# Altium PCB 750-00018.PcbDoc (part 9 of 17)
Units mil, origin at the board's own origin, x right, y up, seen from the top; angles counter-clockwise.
Board outline 7086.64 x 6299.21 mil, 8 copper layers (Top Layer, L2, L3, L4, L5, L6, L7, Bottom Layer), stack 60.6 mil thick; 1356 components, 1054 nets, 4851 pads, 4296 vias.
Unrouted connection lines stored in the file: 12.
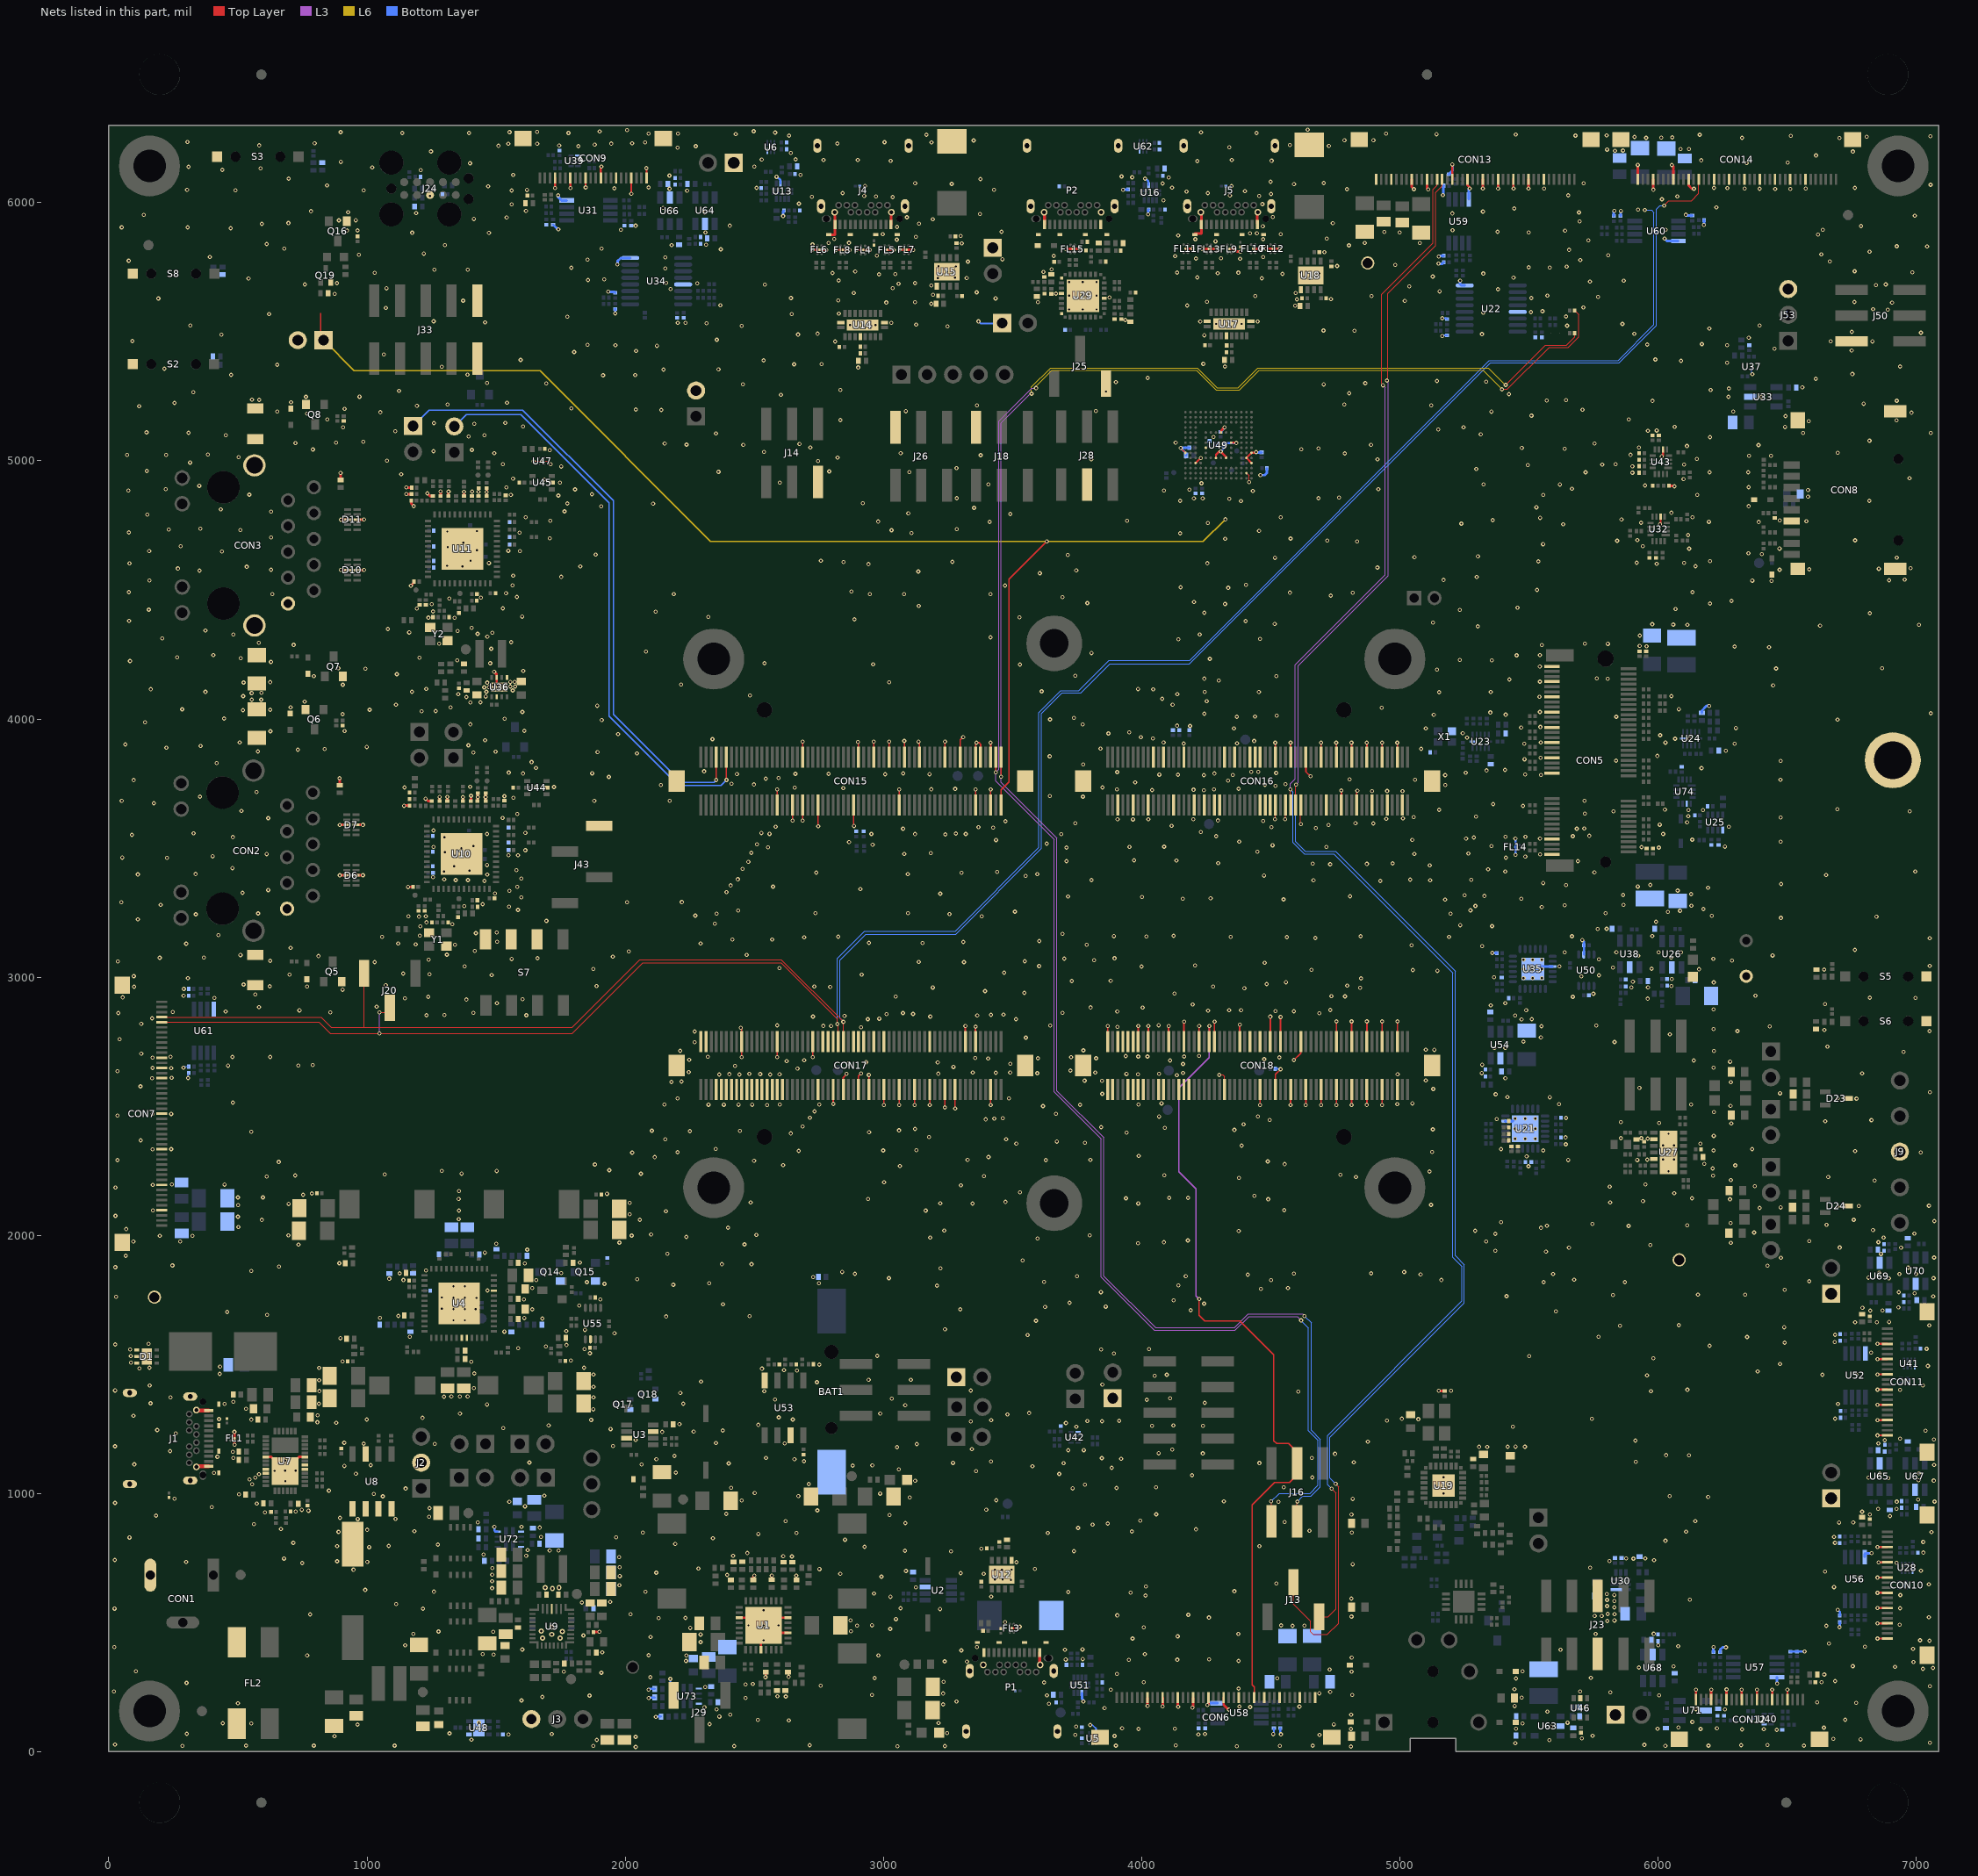
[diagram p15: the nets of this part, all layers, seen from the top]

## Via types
v1: diameter 16, hole 8, Top Layer to Bottom Layer, tented both sides, 3994 vias
v2: diameter 20, hole 10, Top Layer to Bottom Layer, tented both sides, 266 vias
v3: diameter 14, hole 7.87, Top Layer to Bottom Layer, tented both sides, 24 vias
v4: diameter 22, hole 12, Top Layer to Bottom Layer, tented both sides, 8 vias
v5: diameter 24, hole 12, Top Layer to Bottom Layer, tented both sides, 4 vias

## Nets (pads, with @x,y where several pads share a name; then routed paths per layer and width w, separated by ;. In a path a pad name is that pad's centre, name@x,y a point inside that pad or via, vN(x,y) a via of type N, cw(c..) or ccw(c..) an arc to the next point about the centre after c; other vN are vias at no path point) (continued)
GND: (continued)
  other v1: 2040.39,18.82 4368.14,20.94 4810.01,20.35 2421.41,21.87 3054.46,21.3 1876.39,22.46 3238.07,22.13 4534.68,23 285.15,23.13 531.55,23.98 793.94,23.93 1106.78,23.93 3900.09,23.59 4662.13,23.76 6028.07,23.31 6194.82,23.59 6564.89,23.9 4132.2,24.31 2714.05,25.2 6321.21,25.18 5946.82,26.86 6423.69,26.65 23.63,28.08 5447.04,32.94 7052.94,35.05 1890.01,45.72 5578.56,45.43 1404.05,46.32 6784.04,47.82 6678.84,49.85 5704.09,52.16 2040.25,57.91 874.03,60.75 3894.86,60.98 5746.09,62.33 3742.53,65.63 4688.88,65.45 1548.22,66.82 4219.37,67.44 1715.62,68.5 4245.14,68.49 301.65,69.6 1319.18,71.21 3246.05,72.5 6459.01,85.06 6325.13,86.8 6409.37,87.26 3987.17,88.5 4810.26,88.28 5997.65,89.05 6164.12,88.41 4128.44,89.27 5449.73,89.68 3924.07,91.09 6227.52,90.86 6642.11,93.54 6078.3,94.74 3746.14,97.44 5585.11,97.15 963.33,105.19 4743.97,105.64 2326.51,107.27 551.92,109.3 5475.46,109.92 440.82,110.66 3212.96,110.82 5649.39,112.47 1432.99,114.04 6132.32,115.29 2633.46,121.49 2513.96,123.03 6724.06,123.95 2364.45,136.26 2406.13,143.85 4811.16,143.71 5570.84,155.53 6258.85,163.89 2353.34,164.12 6146.24,164.75 3856.06,169 2306.7,172.08 4420.26,173.35 5720.93,173.72 4610.8,174.83 4378.5,175.17 5444.05,177.05 3231.43,183.37 3640.75,186.37 499.98,187.88 6767.15,189.91 6615.87,191.67 3282.63,194.42 1597.93,198.83 2465.48,208.2 5471.68,210.02 1679.32,212.27 2589.35,214.86 2621.67,214.13 1861.75,217.42 3633.01,217.97 6003.3,218.81 4815.53,219.88 2955.7,220.17 3230.93,225.72 4688.2,226.35 5815.4,230.56 4729.88,231.84 5698.07,233.58 19.24,234.11 3880.04,240.58 5443.74,242.04 4375.27,244.61 2309.55,250.42 7053,254.12 2756.8,255.63 2465.47,260.55 2494.02,262.84 301.12,266.62 3621.83,268.53 4007.75,268.91 6632.81,269.56 3232.17,271.05 6685.36,273.47 5449.08,283.79 4524.57,284.45 2965.72,285.7 5739.3,286.64 2097.11,288.98 2632.85,290.38 6643.49,299.15 3904.64,301.59 1907.61,305.96 1762.21,309.83 4812.91,310.43 5474.51,311.73 104.6,312.12 4728.08,318.74 7025.3,321.36 7064.27,324.45 5925.4,326.43 6917.55,328.88 6060.03,330.24 6753.96,331.51 6005.19,333.83 6988.65,348.05 3323.32,349.58 3237.13,350.32 2235.28,352.08 4374.75,351.76 3950.19,355.6 4137.81,356.68 3705.83,357.24 3771.38,358.95 4260.7,358.15 4813.18,365.08 768.12,373.32 2090.42,373.95 2236.34,373.46 2980.07,373.2 1490.35,376.67 1447.82,377.85 4012.29,378.6 1910.88,385.24 3301.56,392.71 3702.59,395.05 5621.87,395.67 1601.16,396.26 3770.48,396.37 6987.11,398.52 20.89,404.97 3361.84,405.19 6800.57,407.15 6077.91,409.12 6000.7,411.95 1147.36,412.23 6661.61,419.47 2291.56,424.99 7051.15,430.15 2535.26,431.68 7014.5,431.7 3964.35,438.45 2097.78,444.6 4139.28,447.13 1837.72,450.4 2291.73,454.1 1178.68,456.73 4374.05,456.29 5757.89,456.56 5982.8,456.97 1488.9,464.79 1276.59,465.57 2874.32,466.8 3025.98,475.9 2251.51,479.64 4008.35,482.34 4584.65,488.02 6650.95,487.66 2897.82,488.61 4630.42,488.39 2477.19,489.75 2593.33,489.75 2955.7,489.79 4539.62,489.51 6935.02,492.09 3470.5,502.54 5803.12,506.65 2872.74,508.71 5830.89,508.51 3048.2,513.63 2129.58,517.15 2233.5,518.66 4260.21,519.88 7048.6,520.61 4812.53,523.35 5781.55,525.72 5754.32,526.49 3905.3,528.39 4180.57,530.2 779.39,531.88 2020.45,532.45 5831.4,533.06 5804.98,533.57 2535.26,547.82 3219.46,552.73 21.99,554.41 1216.18,554.23 3066.52,555.73 6936.79,555.79 5830.55,559.31 5802.46,564.45 1112.97,571.74 1831.83,578 1941.42,580.7 5830.58,584.04 5802.18,588.38 6122.64,589.34 4811.84,593.46 3026.55,600.37 3417,601.1 4014.53,605.04 6937.73,606.63 5830.72,607.13 5801.9,611.33 2963.44,612.7 3956.83,616.66 3715.94,618.77 2078.14,619.83 1258.55,620.13 4358.92,621.84 993.04,626.93 1484.17,633.71 3126.04,636.84 6681.29,637.7 4016.33,639.73 1977.14,644.78 7048.6,648.14 4521.05,651.58 1483.95,660.11 3493.86,665.42 3431.01,667.36 3461.53,667.12 6779.37,675.05 2992.11,678.12 1978.55,680.2 2662.21,682.48 2394.63,684.98 1484.52,686.21 2832.62,689.16 3388.3,689.2 3298.6,691.64 2120.01,693.75 6646.79,697.39 3087.01,700.58 7017.56,701.52 3459.35,704.25 947.27,705.12 3431.25,705.46 3495.8,705.46 2752.1,707.46 3586.04,707.68 2283.35,709.78 1484.93,711.06 5736.53,713 1978.27,714.76 4817.19,726.17 749.06,731.16 6923.43,731.33 3515.05,734.57 299.32,735.37 1001.06,735.33 883.9,737.91 5811.87,738.78 5984.23,741.51 23.08,742.86 5904.04,747.96 678.26,748.2 5876.04,748.98 5949.97,748.68 1976,753.86 2645.28,756.43 2611.64,757.15 1616.52,758.6 2417.53,759.09 1451.34,763.91 2472.29,769.76 7027.15,771.42 3261.78,776.24 3737.25,777.07 3082.66,778.34 1707.18,779.87 1741.61,779.38 1621.64,780.9 3378.57,786.67 1008.06,792.44 2926.16,794.09 4455.68,796.07 883.9,796.12 1083.51,797.01 1274.24,802.14 2193.41,804.89 714.4,809.14 6684.91,809.34 7026.55,812.51 6028.13,817.37 2851.19,821.39 2339.18,826.6 80.11,829.82 1964.67,830.51 1673.9,832.15 6681.29,832.27 2515.12,843.45 2663.56,847.42 3636.55,847.71 4813.2,848.85 2068.17,849.56 889.43,851.76 6108.25,852.1 7058.5,851.18 1183.23,853.92 3961.57,853.4 4649.67,855.58 1000.32,859.86 4209.96,861.56 666.41,863.16 3753.5,866.98 1668.7,868.34 1598.13,870.79 3810.01,880.13 561.66,881.12 3868.27,884.07 3084.51,885.49 6701.05,887.67 6755.64,888.08 1429.06,888.68 4553.95,890.28 2620.81,893.73 6143.99,893.53 3994.04,895.33 963.78,901.24 1109.98,902.25 895.48,906.28 1240.58,910.07 6897.99,912.71 182.57,914.57 3023.4,916.84 4812.51,918.96 6820.02,918.68 4056.17,919.66 2390.97,921.23 604.85,927.62 6789.93,930.08 723.64,930.39 773.27,933.58 2743.82,934.75 747.27,936.99 3398.12,937.3 6923.05,940.65 6851.61,941.11 1241.65,943.35 398.32,947.87 1611.83,950.52 572.93,961.08 23.63,963.72 1550.75,967.87 4530.08,967.87 6924.31,968.6 7070.71,969 4318.35,970.26 2451.06,972.89 3436.95,974.19 7007.12,977.09 254.64,979.59 4817.42,979.44 3101.63,985.4 6193.54,987.27 1060.91,989.31 2670.49,989.97 6044.08,990.57 1686.4,992.24 503.87,996.57 1026.01,998.64 2986.86,999.84 5168.69,1000.24 2501.12,1002.11 852.04,1011.22 1149.05,1019.63 3732.35,1020.29 2409.94,1022 3902.53,1021.52 4055.17,1023.83 4550.19,1024.45 5137.19,1031.74 5168.69,1031.74 5200.19,1031.74 3780.45,1034.19 554.84,1036.09 2711.08,1037.14 683.33,1047.51 3122.75,1049.59 7067.35,1050.27 7008.65,1051.78 544.9,1054.62 6891.02,1059.42 566.59,1061.15 6814.71,1061.43 4660.54,1062.58 5168.69,1063.23 4194.97,1070.96 581.7,1075.59 3680.5,1075.88 956.84,1076.86 6858.85,1078.05 7009.73,1078.65 407.66,1080.41 2195.47,1080.9 3357.98,1086.71 642.01,1087.88 682.37,1088.36 723.22,1088.36 3058.89,1094.15 3883.28,1099.81 3576.93,1105.43 912.6,1107 2880.48,1108.38 1014.58,1110.01 2956.67,1109.32 7068.64,1110.64 2062.69,1113.02 98.77,1113.14 2400.28,1116.99 3269.07,1118.86 3697.61,1118.1 4455.95,1118.26 1628.68,1120.41 4821.46,1121.6 5913.79,1123.15 3415.83,1124.76 2691.57,1125.51 682.37,1128.24 2120.32,1132.78 2655.16,1132.61 3920.32,1134.84 3845.32,1137.4 481.6,1138.59 2545.03,1138.35 4659.2,1138.4 420.21,1142.5 2190.65,1145.54 6030.73,1148.85 6119.09,1148.59 4748.49,1153.96 4236.36,1155.61 4065.2,1156.3 480.72,1162.15 237.68,1164.46 3715.61,1167.72 3775.59,1168.14 4118.82,1170.76 3342.1,1172.12 3052.24,1179.56 5338.31,1180.97 5307.03,1181.16 5417.35,1181.37 5448.18,1181.76 5484.05,1181.57 23.63,1182.94 1952.67,1183.88 487.5,1188.71 3128.68,1191.57 1262.79,1192.41 986.54,1193.32 2617.63,1194.59 6852.75,1194.6 911.52,1196.63 2351.01,1196.16 4875.71,1201.42 5911.91,1205.02 6877.12,1207.04 2040.15,1208.29 7068.08,1209.19 6937.05,1212.83 259.67,1233.24 2143.28,1238.97 2264.84,1239.82 7035.59,1243.23 2377.84,1244.46 187.38,1246.07 1943.22,1249.75 1527.83,1253.53 3746.85,1258.77 5437.57,1258.65 4039.8,1262.31 4237.63,1262.13 1703.17,1264.09 4122.49,1263.54 2515.2,1266.18 2209.79,1268.81 3706.37,1273.38 880.88,1274.5 807.81,1276.37 3337.91,1278.95 3846.67,1279.99 3789.45,1280.6 3912.6,1281.78 4949.77,1282.82 3417.11,1284.18 1868.08,1285.23 551.49,1286.59 998.33,1286.72 2648.49,1286.93 426.88,1288.75 5071.3,1288.28 5007.2,1289.99 5743.87,1289.12 6684.98,1290.27 1214.99,1293.36 2594.4,1295.26 95.27,1300.87 808.77,1303.34 3479.99,1305.93 1359.81,1309.86 2987.26,1310.19 3563.85,1312.06 1876.49,1326.21 531.4,1328.13 3084.24,1342.24 1464.28,1344.91 447.75,1347.4 2224.44,1348.06 6696.56,1347.63 813.91,1348.29 161.73,1349.84 4243.85,1351.25 481.82,1355.73 4020.06,1363.19 2580.11,1364.12 3032.17,1367.74 4110.15,1369.36 1876.71,1373.04 238.68,1373.16 1297.61,1375.2 1358.93,1375.64 1389.28,1375.83 1326.4,1376.51 2213.15,1389.68 4606,1395.15 5972.16,1396.01 815.19,1397.09 2538.24,1396.24 5197.71,1397.93 3337.91,1398.88 24.18,1399.4 6936.81,1401.37 6113.17,1402.16 1413.58,1408.55 1876.94,1413.05 158.23,1418.63 7025.72,1418.14 3847.52,1422 2742.03,1431.42 2293.4,1434.01 814.55,1439.47 2942.51,1440.88 3106,1440.23 4050.81,1455.64 5957,1457.22 1876.94,1461.02 4097,1460.44 6636.18,1460.25 6767.81,1461.59 429.25,1463.78 1415.5,1465.42 6385.18,1472.75 2664.6,1476.39 2614.92,1477.77 2529.4,1483.71 118.56,1484.68 814.23,1486.67 157.58,1487.22 1840.79,1487.7 430.43,1491.77 7044.68,1494.1 2751.52,1499.36 6472.31,1502.18 85.59,1506.92 1403.09,1510.37 905.09,1511.71 1789.71,1515.99 5981.7,1524.32 84.81,1532.67 5500.93,1532.87 2975.9,1533.34 3892.38,1542.99 1862.95,1543.66 6825.1,1546.12 82.86,1557.84 3842.59,1558.15 1842.43,1559.83 4028.71,1559.4 7039.99,1560.8 1585.63,1563.57 1692.37,1570.05 6198.92,1572.56 1772.62,1575.59 24.73,1577.41 153.66,1580.54 6490.05,1584.48 6684.18,1587.26 897.06,1601.61 1165.53,1607 6344.64,1606.69 5768.77,1607.15 3558.17,1613.82 6685.9,1614.89 1958.21,1620.68 1531.9,1627.16 1771.52,1628.92 1843.97,1633.95 3238.32,1635.91 6487.91,1644.21 5852.65,1649.66 7049.91,1651.68 6079.84,1652.45 6762.91,1663.82 6846.72,1663.82 6894.44,1664.57 3590.48,1669.41 1334.73,1671.04 1378.63,1671.04 1678.5,1677.71 1609.1,1679.82 1050.31,1680.19 2157.92,1686.03 2480.8,1686.94 1121.28,1687.98 613.37,1691.84 458.25,1703.41 5604.47,1705.73 6820.95,1708.56 6868.82,1709.53 4189.99,1710.39 1420.57,1714.1 1639.98,1713.49 3297.61,1713.55 1334.73,1714.94 1378.63,1714.94 1290.01,1715.8 6791.37,1719.26 6930.74,1721.02 3625.89,1723.26 3860.72,1724.05 1821.37,1727.74 2378.62,1732.74 4241.64,1735.59 3721.07,1739.31 4123.64,1748.65 1607.77,1752.05 1903.31,1751.89 1423.35,1757.96 1334.73,1758.83 1378.63,1758.83 1290.01,1759.7 28.03,1762.01 7065.17,1763.34 5412.99,1764.53 5825.04,1769.2 6154.41,1770.65 6337.26,1770.59 6993.52,1775.41 6932.1,1780 3842.07,1780.14 1466.51,1786.81 6490.16,1789.17 4461.42,1792.75 1639.69,1796.48 4566.46,1796.35 1334.73,1802.73 1378.63,1802.73 3207.14,1805.19 4141.7,1806.02 2186.01,1808.64 1919.62,1812.11 2325.02,1814.98 2750.33,1815.05 1851.23,1818.77 5871.5,1818.85 5557.08,1819.18 3622.22,1820.13 6585.32,1822.33 1654.72,1826.54 4501.28,1826.27 1140.59,1827.11 5160.67,1827.12 5674.77,1828.71 2045.95,1829.72 1086.03,1832.23 6893.74,1833.44 3020.79,1834.38 7066.77,1834.12 6814.69,1836.29 2727.36,1838.57 3749.44,1841.52 4170.53,1841.58 4410.36,1848.04 5080.05,1848.88 6934.53,1849.94 6998.8,1849.94 5593.12,1850.31 2888.99,1851.37 4589.7,1851.8 1126.31,1853.07 4888.21,1852.9 1751.47,1853.9 6856.3,1855.68 5016.53,1857.97 2840.26,1858.38 551.7,1862.19 1228.63,1863.96 3220.34,1872.69 6968.71,1874.85 25.28,1876.84 658.9,1879.81 6423.69,1882.23 246.3,1883.51 2374.21,1888.4 2488.76,1888.4 1610.83,1890.79 892.52,1892.03 1824,1894.36 3538.73,1902.94 6475.46,1913.26 7069.03,1913.92 65.51,1921 6862.91,1928.08 2163.11,1928.58 1455.81,1933.16 5565.66,1936.69 5369.63,1940.88 1620.06,1944.81 5654.69,1952.15 6703.3,1952.98 6941.02,1952.29 5969.79,1962.47 734.28,1963.83 2461.85,1965.3 1500.56,1967.75 3985.53,1969.07 6281.44,1971.04 1977.14,1972.08 4086.35,1973.35 6852.98,1973.52 5333.54,1975.82 94.91,1976.11 276.65,1976.18 6585.32,1978.31 4178.82,1980.55 3596.9,1987.8 3181.01,1991.55 6873.03,1991.75 2236.07,1993.87 197.45,1998.01 323.69,1998.31 695.52,1999.61 2024.9,1999.25 3798.43,2000.36 2507.67,2001.49 2099.88,2003.35 5369.63,2006.08 6992.46,2007.02 6371.96,2011.12 4375.67,2017.03 5290.9,2017.75 3235.24,2018.55 6832.17,2019.97 66.89,2024.34 2398.27,2029.82 5545.99,2029.48 501.62,2032.48 5885.51,2036.4 5569.54,2037.18 6112.71,2038.83 6652.27,2040.56 5744.9,2044.66 6280.61,2048.04 5391.86,2050.54 7069.35,2055.16 592.73,2060.09 2055.85,2060.5 6757.59,2060.46 1355.2,2062.6 499.79,2072.2 25.71,2075.61 2016.83,2081.34 2157.51,2093.3 3163.49,2096.06 170.87,2096.94 1355.48,2096.19 4552.03,2097.84 6392.7,2106.36 6474.37,2108.29 6694.87,2111.83 6776.87,2114.08 7048.69,2114.84 500.31,2116.89 5120.36,2117.98 696.37,2121.85 3344.41,2123.51 3986.66,2123.54 3219.75,2124.57 2017.3,2126.16 2485.52,2127.94 5814.11,2127.51 3471.95,2129.8 5941.4,2132.81 4489.86,2139.93 6278.13,2139.94 1354.66,2141.24 2940.25,2141.33 3939.11,2143.53 6131.64,2143.9 4106.59,2145.21 4179.33,2145.21 499.79,2146.94 596.79,2147.23 4436.31,2152.73 752.19,2157.36 1929.28,2160.95 786.66,2162.52 6062.19,2162.89 3528.47,2166.15 1355.75,2171.69 25.71,2185.81 5812.41,2188.88 6374.79,2190.3 3300.03,2193.91 170.28,2195.56 243.66,2196.98 448.2,2196.7 5950.76,2197.37 3002.06,2205.29 6838.37,2212.99 6281.44,2214.45 4376.62,2222.9 4829.71,2226.06 6658.76,2226.41 610.85,2228.07 3389.13,2229.72 6212.68,2230.93 721.89,2232.31 4088.01,2232.49 4769.49,2234.88 1068.21,2236.3 2060.41,2238.8 1365.83,2239.21 5114.21,2247.57 6040.4,2248.14 1502.31,2249.37 1289.9,2250.41 1938.3,2252.56 6211.4,2259.44 5497.7,2267.54 3063.3,2268.39 6298.47,2271.42 2611.46,2272.24 1882.29,2274.33 4553.93,2275.99 6179.3,2277.27 658.04,2284.46 4488.19,2286.65 2498.76,2289.09 33.02,2291.53 3628.77,2291.73 5651.51,2291.9 5919.27,2291.89 3325.59,2292.32 3801.53,2292.25 5957.89,2293.43 6018.74,2293.81 6062.05,2293.81 2113.84,2303.22 3406.57,2303.53 5490.84,2305.63 3988.35,2307.33 2026.76,2320.5 7016.94,2321.37 2201.98,2322.34 5124.83,2322.89 6763.02,2326.53 2671.97,2327.19 5555.24,2329 6214.84,2328.91 2998.85,2329.16 3126.93,2329.55 169.34,2333.51 241.54,2334.01 5391.8,2334.04 2350.23,2334.51 6363.74,2334.18 4387.01,2347.56 6018.74,2348.14 6062.05,2348.14 5642.62,2352.87 6163.81,2355.03 3514.3,2355.58 3779.94,2358.71 3671.36,2363.27 123.62,2367.95 2155.26,2372.81 3475.01,2372.59 5445.89,2373.8 5485.26,2373.8 5524.63,2373.8 5959.56,2374.66 5856.15,2376.37 5934.7,2376.5 5641.81,2379.65 3176.99,2380.69 6215.27,2385.4 6040.4,2393.81 2640.9,2394.94 3941.57,2397.98 2944.21,2399.29 551.84,2401.72 2249.65,2403.62 2444.14,2405.09 2103,2405.7 3060.27,2406.85 4358.89,2408.54 5127.45,2410.42 3121.99,2412.25 5445.89,2413.17 5485.26,2413.17 5524.63,2413.17 4089.33,2416.83 3843.25,2419.17 2686.95,2422.11 4394.52,2429.74 6283.5,2433.98 6003.71,2435.51 5856.04,2438.15 6647.26,2442.21 6825.98,2446.26 4496.12,2447.2 3395.44,2449.37 5374.77,2450.56 3429.15,2452.56 5485.26,2452.54 5524.63,2452.54 3462.52,2453.9 5643.27,2454.98 2714.99,2455.97 4067.5,2460.15 4449.87,2460.73 33.02,2464.48 241.29,2470.41 3667.71,2470.94 169.59,2471.16 6216.29,2477.58 2733.3,2480.12 3617.72,2500.65 6280.28,2502.02 3001.88,2504.74 3060.93,2504.74 3119.99,2504.74 3179.04,2504.74 3415.26,2504.74 4458.5,2504.58 4576.62,2504.58 4635.67,2504.58 4694.73,2504.58 4753.78,2504.58 4812.84,2504.58 2322.29,2506.04 2381.62,2506.04 2438.38,2506.04 2491.16,2506.04 2549.09,2505.34 3761.66,2505.86 2151.6,2506.65 2598.14,2506.5 2751.9,2506.76 3987.34,2506.66 6128,2506.72 2805.6,2509.02 4989.57,2508.64 5616.2,2508.44 4076.87,2511.18 5048.13,2511.2 480.03,2514.19 6768.18,2529.38 2202.37,2530.8 3485.75,2530.43 6695.43,2530.58 5580.67,2534.97 5416.34,2535.39 5370.78,2546.52 3847.22,2548.47 6471.82,2550.29 7052.46,2554.42 5128.81,2566.74 5927.77,2571.58 122.67,2577.03 2178.34,2594.08 6281.68,2593.27 2217.93,2595.8 3846.42,2598.02 3778.92,2599.09 5100.16,2600.3 167.57,2608.21 5408.2,2608.28 242.91,2609.94 4136.14,2620.92 2442.17,2623.03 2363.81,2623.27 2561.35,2623.3 3985.97,2623.47 4991.05,2623.84 2403.23,2624.48 2522.58,2624.9 2597.45,2624.37 3940.97,2625.08 2480.63,2625.2 4066.96,2626.03 3212.62,2626.17 6789.85,2626.9 3595.73,2628.41 5316.53,2628.49 3434.69,2630.08 4160.04,2629.46 3490.54,2630.41 3820.17,2630.97 2245.97,2632 3345.58,2631.13 33.51,2635.49 3723.74,2638.47 2667.11,2645.64 241.42,2647.61 169.3,2648.6 6214.64,2649.12 3270.83,2652.3 2425.27,2656.57 461.51,2657.35 733.3,2658.3 789.88,2659.41 5318.35,2660.74 4160.08,2663.93 3491.06,2664.52 2864.26,2666.07 2932.37,2670.49 3209.98,2670.16 6278.52,2672.7 2624.93,2675.27 4109.47,2677.72 6138.19,2677.58 2693.14,2678.44 2247.28,2680.07 4474.71,2682.44 3405.01,2684.67 3598.59,2685.74 3355.17,2687.03 3823.38,2686.15 169.06,2688.26 2450.69,2689.78 2588.49,2689.78 2726.29,2689.78 4533.15,2689.45 478.18,2691.04 3726.68,2690.17 239.38,2691.8 624.91,2691.19 2320.13,2691.67 3986.78,2692.84 4022.14,2692.58 4164.21,2692.8 3937.76,2694.45 4221.87,2694.89 125.59,2703.7 6950.88,2710.51 6215.96,2713.83 2212.98,2714.81 3774.36,2716.42 5133.76,2718.59 5100.16,2719.48 5366.65,2725.47 5407.91,2726.41 6655.67,2731.15 2268.93,2747.96 5831.05,2749.07 5478.16,2750.52 41.3,2760.22 3551.19,2765.84 5545.82,2767.16 6045.17,2778.79 2268.93,2789.61 6307.1,2791.26 7051.2,2791.17 6643.65,2795.48 6214.97,2798.95 2912.6,2805.6 3905.79,2807.25 3356.49,2808.17 6432.48,2808.93 5548.51,2809.9 2796.91,2810.81 3317.12,2810.54 3868.3,2810.54 3986.41,2810.54 4025.78,2810.54 4104.52,2810.54 4222.63,2810.54 2767.1,2811.44 3645.68,2812.25 5760.58,2812.74 2588.43,2813.29 4066.16,2813.78 4379.9,2816.4 125.59,2819.65 4164.25,2828.35 4282.36,2828.35 5471.01,2836.54 5510.57,2837.05 2939.63,2837.29 3513.56,2837.4 2983.49,2839.33 167.07,2840.48 2726.67,2847.35 3181.07,2847.69 2848.97,2850.03 3362.98,2852.02 5446.55,2851.9 1230.06,2852.37 1616.54,2852.6 1300.06,2853.8 3415.98,2854.33 3464.6,2855.11 3011.53,2857.32 3114.49,2857.52 4688.05,2860.09 36.92,2861.07 3075.65,2860.87 1412.26,2861.48 3693.62,2861.81 857.66,2863.96 247.21,2864.93 452.09,2867.21 3905.34,2867.51 4589.72,2867.72 4517.8,2869.23 4257.07,2870.29 738.21,2871.56 5489.13,2872.02 4338.69,2872.18 4384.74,2872.51 4730.73,2872.83 6214.11,2875.5 3802.5,2882.89 4003.8,2882.51 581.3,2884.04 1036.95,2885.42 5351.55,2891 4197.23,2893.84 6646.8,2896.13 1503.08,2898.87 5407.95,2899.38 1384.52,2913.46 1601.98,2915.05 5959.51,2916.91 1146.36,2917.6 408.76,2919.75 6996.2,2919.43 6819.61,2920.76 53.29,2921.94 1236.96,2924.04 3047.08,2924.56 5669.86,2924.23 4787.27,2925.9 4734.64,2926.6 289.4,2927.93 6376.72,2928.22 567.5,2932.95 5749.22,2935.72 4126.99,2937 3545.36,2939.18 3393.23,2946.07 904.88,2951.46 290.45,2954.54 4397.68,2956.84 4845.69,2958.65 3190.92,2960 5896.53,2960.15 5960.67,2960.73 2793.48,2961.94 97.88,2963.12 767.47,2963.5 2732.13,2963.62 4276.06,2963.5 623.43,2964.55 1888.84,2965.73 6051.26,2965.48 4795.83,2967.5 1072.5,2969.12 521.99,2971.82 4483.8,2973.4 6215.27,2979.8 4558.95,2980.43 5902.21,2982.51 3728.9,2985.21 3879.84,2986.11 6053.35,2992.35 4849.23,2995.53 306.21,2996.31 5478.96,2996.43 5514.39,2996.43 5549.82,2996.43 5364.98,2999.16 96.64,3003.82 5702.94,3003.28 5770.93,3007.49 1482.7,3008.48 699.77,3009.62 2915.75,3010.03 1241.48,3011.78 1140.35,3014.21 3466.79,3017.61 5145.59,3024.55 5050.27,3027.67 4657.76,3028.91 6642.45,3029.41 6158.5,3030.78 5478.96,3031.87 5514.39,3031.87 5549.82,3031.87 1876.2,3032.17 5974.63,3032.6 2596.94,3034.85 5825.45,3037.21 3999.06,3041.24 1378.02,3042.29 5618.05,3042.1 3602.76,3043.19 7051.7,3043.76 4206.75,3045.97 4476.04,3055.45 1029.13,3058.44 3136.72,3059.02 3311.57,3058.13 3547.48,3061.63 6286.07,3063.89 3815.92,3065.77 1238.29,3067.5 5478.96,3067.3 5514.39,3067.3 5549.82,3067.3 5770.35,3069.2 1560.22,3070.52 3699.75,3071.9 6213.71,3071.22 1659.9,3073.45 3894.65,3073.3 6050.56,3075.74 1951.44,3079.21 812.22,3081.76 5922.95,3083.14 6443.42,3084.08 2469.95,3086.39 1309.26,3087.37 5638.49,3096.37 5838.22,3096.36 6001.74,3097.03 6088.81,3097.03 2013.81,3099.49 1416.73,3101.84 6761.7,3105.67 703.88,3113.79 5318.45,3120.32 5044.66,3123.61 1340.95,3125.14 3787.08,3125.22 1188.32,3127.25 1120.13,3130.09 2291.47,3130.12 3151.02,3131.89 2943.83,3133.23 1503.98,3136.98 3309.11,3136.42 3603.62,3139.95 2415.3,3145.88 2568.62,3145.85 4672.72,3151.65 7051.85,3151.38 2693.1,3154.68 4562.11,3154.95 4344.16,3155.74 5190.2,3155.89 1058.39,3156.35 2824.8,3157.09 4017.81,3157.54 3892.72,3158.93 4848.02,3158.4 5666.08,3158.81 5977.19,3159.66 4123.04,3160.48 1204.93,3161.19 3692.91,3167.62 1421.35,3170.63 1501.72,3172.71 5765.52,3187.04 5800.7,3187.3 1205.99,3196.35 5357.06,3197.45 5233.99,3201.35 1330.51,3205.17 2347.38,3207.46 1229.94,3212.71 5991.48,3214.66 1694.66,3217.99 6475.62,3229.69 1201.41,3234.78 6845.79,3234.12 1227.66,3235.92 3380.81,3235.82 1160.35,3236.32 6208.13,3237.36 2271.39,3238.7 3255.53,3244.21 2353.89,3245.74 5196.06,3246.29 3094.9,3247.41 5796.29,3247.96 2736.34,3248.23 3508.97,3253.8 6037.22,3253.35 6084.77,3257 2437.27,3258.03 5273.24,3259 1584.23,3260.45 6175.36,3263.78 5549.28,3271.95 1549.64,3273.11 1376.14,3275.14 5292.11,3275.75 6128.87,3277.14 5638.37,3278.38 5865.8,3280.14 1447.77,3282.51 2007.24,3290.3 2218.93,3290.91 5174.9,3300.41 4549.28,3301.43 4159.66,3304.04 5469.51,3304.06 4266.87,3305.73 1597.27,3309.25 4001.24,3310.53 3714.75,3312.27 4806.67,3313.4 5326.82,3314.73 5250.54,3317.37 5864.81,3318.5 6127.8,3321.57 3219.82,3323.27 1495.71,3324.56 2391.85,3329.8 1551.36,3334.36 6075.67,3335.63 2910.5,3341.17 6193.11,3346.11 1582.23,3349.48 2572.12,3350.69 5921.14,3351.01 2407.99,3355.51 5643.53,3356.62 5969.96,3357.45 6476.41,3360.89 5555.14,3364.6 1454.7,3373.04 4924.62,3372.76 1343.12,3376.02 3805.7,3375.97 4665.27,3375.51 5117.34,3375.28 1390.48,3376.44 5039.92,3377.81 5275.92,3377.31 1298.89,3379.16 2435.9,3379.34 1596.73,3382.28 1255.99,3387.04 3550.11,3391.85 4473.58,3393.45 894.51,3394.6 984.09,3394.93 6650.58,3396.22 1465.37,3397.76 3094.27,3398.68 3595.68,3399.47 3302.21,3403.76 2740.11,3404.92 5753.21,3405.74 3440.56,3408.1 5407.96,3409.02 6995.76,3408.94 1298.2,3409.46 1396.95,3412.88 1578.95,3414.74 5341.32,3418 2453.6,3419.16 1336.74,3430.21 5115.66,3433.35 1464.86,3434.27 4729.81,3437.56 4872.03,3438.82 4662,3440.13 4972.17,3440.92 4296.06,3441.75 2476.74,3446.73 3708.71,3449.07 5689.57,3449.37 4134.31,3451.96 3970,3452.69 5410.45,3463.14 5485.74,3467.48 1547.6,3471.87 1584.39,3472.18 5542.74,3475.57 3080.65,3476.87 5056.17,3477.82 5265,3479.33 2487.97,3481.44 3183.31,3481.12 1301.16,3484.5 4448.12,3485.47 1613.09,3491.91 1365.02,3499.55 3708.71,3501.91 6003.05,3501.97 2552.53,3502.86 5936.18,3503.63 1257.18,3504.89 3952.63,3504.8 4714.91,3504.11 4086.7,3505.53 6258.89,3505.72 5354.17,3507.91 1411.78,3508.44 4506.67,3510.77 2957.77,3512.84 2510.43,3515.13 3632.6,3517.18 2866.56,3523.53 4377.54,3524.53 6474.43,3524.97 3435.82,3531.17 5047.77,3532.07 6131.86,3532.78 5256.22,3536.73 5542.5,3536.58 5286.36,3541.09 1300.25,3541.74 5486.19,3543.56 5408.87,3544.13 4288.58,3546.4 5669.79,3546.23 5733.42,3547.63 3239.07,3553.19 3687.82,3553.74 1464.57,3554.64 2558.42,3554.95 2952.82,3554.51 3122.04,3554.37 3318.52,3554.77 6019.59,3554.68 3280.67,3556.15 1613.1,3559.09 2527.11,3558.36 4229,3562.15 1256.78,3568.48 3075.72,3574.9 5685.11,3575.32 5713.98,3576.33 4674.41,3577.51 3424.31,3579.42 3367.82,3580.98 4502.51,3581.47 2582.24,3582.52 6273.72,3582.41 4115.63,3586.26 894.51,3589.76 984.09,3590.09 4723.19,3589.75 6006.23,3590.71 3742.68,3595.99 4897.19,3595.27 4827.88,3596.75 6112,3599.44 3472.43,3604.03 4470.36,3604.4 2647.55,3606.22 2686.92,3606.22 4295.06,3607.09 3966.06,3611.07 3906.4,3611.82 4025.71,3611.86 4200.17,3611.24 4947.36,3613.02 5011.54,3614.93 1524.95,3616.95 6474.43,3618.34 5053.78,3620.09 5294.52,3622.17 6116.75,3623.86 1581.71,3631.61 5716,3633.85 6974.22,3641.77 5827.2,3642.38 6173.89,3646.95 6117.5,3647.1 5152.42,3648.38 6026.32,3648.71 6694.16,3650.92 5476.94,3663.44 5360.71,3670.41 5714.89,3682.74 1879.97,3683.18 2171.34,3683.27 1566.29,3694.8 3772.53,3699.18 1531.82,3700.97 3644.26,3701.52 4892.36,3720.84 4950.71,3720.98 5009.82,3720.81 4240.99,3723.81 4773.16,3723.13 4039.79,3724.5 4200.97,3726.06 2588.68,3727.54 3061.12,3727.54 3185.19,3727.8 3356.4,3727.54 3415.45,3727.54 3903.95,3727.28 4280.1,3727.23 3277.81,3729.5 4375.14,3729.75 2844.21,3732.52 1144.79,3734.85 2656.39,3734.17 3848.07,3734.81 1724,3736.81 1399.28,3737.79 1654.09,3739.17 4517.66,3741.01 2137.48,3744.65 4477.24,3745.08 5176.05,3744.12 2498.64,3746.47 4556.6,3748.07 2411.35,3749.03 3974.75,3754.03 4334.23,3760.85 5058.12,3764.8 6473.86,3764.9 4804.97,3766.13 2544,3769.11 893.4,3770.61 2593.25,3771.8 1936.42,3775.66 4241.01,3782.55 5175.2,3782.61 5546.05,3782.85 4140.97,3784.07 4353.2,3783.7 4068.24,3784.55 3006.58,3785.95 5484.96,3785.31 2432.49,3786.75 3178.49,3786.24 2658.93,3787.6 2787.14,3787.5 1603.57,3788.99 3076.1,3789.06 4281.16,3788.96 1871.85,3789.63 4520.7,3790.85 1548.59,3792.39 5254.76,3792.22 3904.97,3794.55 4424.11,3795.19 4451.51,3795.39 2305.15,3797.55 5335.32,3800.85 5407.07,3803.02 6168.11,3809.51 1653.94,3810.48 3772.78,3824.46 1636.94,3833.22 6474.87,3837.26 5837.59,3838.74 5482.65,3844.02 5544.25,3849.36 3643.48,3855.53 5996.87,3857.04 2045.37,3866.88 1411.65,3870.06 1892.51,3871.88 1497.58,3873.67 6262.24,3876.86 732.29,3881.3 835.18,3883.36 5082.6,3884.42 3840.67,3885.84 998.79,3891.59 1392.52,3898.2 4162.37,3904.75 5482.11,3904.39 6295.62,3904.2 4369,3905.57 4517.25,3908.17 4576.31,3908.17 4694.42,3908.17 4753.47,3908.17 4812.53,3908.17 4871.58,3908.17 4930.64,3908.17 4989.69,3908.17 5545.43,3908.86 6028.12,3908.57 4084.92,3909.52 2687.11,3912.58 2962.7,3912.58 3021.75,3912.58 3238.29,3912.58 3080.71,3914.94 4435.46,3914.77 1457.18,3918.07 2337.54,3922.1 6065.99,3923.61 6121.39,3923.97 4043.56,3924.55 5260.19,3928.02 3996.9,3929.63 6008.17,3937.35 1972.19,3940.99 3870.91,3943.95 5243.28,3945.27 3952.27,3947.8 912.83,3953.29 1609.02,3954.43 4357.11,3963.7 5100.16,3963.33 6301.29,3964.7 5469.34,3966.52 5543.85,3969.16 4187.41,3972.81 4137.15,3974.29 3771.76,3978.91 1400.2,3979.43 1908.9,3996.26 6694.87,3997.52 3645.04,3998.64 1532.22,4001 3737.77,4004.4 4367.98,4008.64 5837.79,4008.6 4438.94,4009.7 4522.99,4012.44 5131,4015.88 5409.36,4016.8 905.08,4018.73 4242.48,4020.68 7056.12,4021.96 5349.87,4025.29 1601.62,4027.42 5542.15,4027.16 1210.85,4030.15 1265.85,4030.85 519.7,4034.12 625.06,4035.86 1010.11,4035.65 6080.31,4037.78 4929.09,4043.36 703.72,4044.66 1323.96,4044.79 1891,4051.43 1111.98,4055.2 4119.5,4055.52 1399.69,4064.29 1439.2,4064.58 758.24,4067.65 4251.66,4068.47 553.84,4074.66 589.98,4074.82 4078.93,4078.42 1384.4,4085.05 5540.29,4085.52 1459.12,4087.07 520.15,4088.49 6051.79,4088.72 2483.12,4091.45 1353.25,4096.01 4137.96,4095.68 552.86,4100.49 590.47,4101.48 5151.9,4103.82 4243.95,4104.48 5351.96,4104.5 1173.71,4105.62 1461.99,4105.29 4453.82,4105.13 3612.39,4107.38 1563.91,4110.57 1488.85,4114.02 1504.41,4114.02 1519.98,4114.02 1535.54,4114.02 4044.42,4114.37 3985.75,4115.96 1229.25,4116.27 1453.39,4122.4 1471.22,4122.87 1554.32,4125.87 1573.25,4125.69 6445.15,4130.37 906.13,4132.84 1488.85,4132.4 1504.41,4132.4 1519.98,4132.4 1535.54,4132.4 2216.38,4133.74 1465.33,4140.94 522.13,4141.21 624.71,4142.6 3022.18,4142.54 1554.59,4143.18 1572,4143.72 5541.95,4144.42 4298.26,4148.69 5424.34,4153.28 5804.66,4155.44 4242.74,4156.21 5762.49,4157.4 793.93,4165.96 4521.61,4166 3742.78,4167.21 1115.06,4173.53 1604.77,4186.43 5143.86,4191.64 889.38,4195.97 993.64,4195.14 6456.76,4195.81 6867.33,4196.91 5541.81,4203.32 3528.03,4210.93 2959.6,4211.39 2539.23,4215.88 1477.03,4216.1 1348.93,4226.95 5355.91,4226.86 5231.61,4229.03 4263.6,4232.95 1202.53,4237.32 5451.87,4246.75 5542.17,4247.05 3805.67,4255.41 2079.75,4261.42 1480.68,4272.18 6429.61,4277.76 6296.15,4280.56 5955.42,4281.51 5928.37,4283.07 5549.34,4286.32 715.99,4287.13 1279.21,4291.55 5716.43,4291.37 5805.36,4291.1 1557.99,4297.4 4141.76,4308.97 4458.3,4310.53 3415.06,4316.48 1465.75,4318.96 5928.44,4323.02 4224.62,4327.61 1428.25,4329.92 1485.25,4333.93 1163.16,4335.31 1350.8,4340.5 1080.08,4348.45 1404.79,4352.54 5301.82,4358.75 6627.05,4361.8 6113.5,4364.76 6058.68,4365.77 7009.85,4365.11 5977.22,4367.03 4515.01,4367.81 5127.84,4373.25 4402.12,4379.34 2887.66,4386.14 1237.53,4392.53 1338.84,4392.16 3526.49,4393.47 2321.28,4395.6 1601.02,4396.51 6819.28,4409.86 4242.61,4411.31 2117.16,4415.94 1255.31,4416.74 5232.38,4422.08 6067.43,4426.08 1192.73,4427.89 1525.63,4428.46 5455.67,4430.97 3136.53,4437.77 1250.16,4444.39 4322.89,4445.38 6200.79,4447.12 3789.57,4448.69 4202.41,4452.99 6283.93,4457.57 1318.38,4467.09 1440.48,4470.45 3692.93,4471.7 1579.84,4472.9 4732.1,4477.63 3080.03,4483.59 2187.91,4484.25 2946.63,4484.18 3415.06,4484.16 1538.29,4487.38 4817.2,4488.9 4574.09,4489.44 6133.22,4491.16 2875.42,4493.55 5531.25,4500.01 4334.9,4508.07 4151.05,4510.31 3470.69,4516.85 1563.14,4517.56 4403.65,4519.15 6438.66,4535 6364.62,4535.92 6894.56,4537.4 5168.7,4538.67 6954.7,4539.92 1751.76,4550.66 5297.24,4550.28 1565.55,4555.12 3605.49,4564.51 3134.71,4571.32 3746.62,4576.01 898.45,4576.91 988.03,4576.91 6470.19,4577.89 6584.66,4580.04 6854.56,4581.8 6977.69,4583.69 4912.88,4586.47 1369.31,4590.77 1826,4590.76 6144.59,4591.61 1309.77,4593.35 2941.72,4599.94 5994.44,4601.04 1471.94,4603.96 4254.51,4603.35 6100.16,4604.86 5917.32,4605.44 2844.84,4607.41 3266.68,4608.7 5535.72,4610.51 6201.19,4611.23 1401.02,4612.93 2757.27,4612.71 4516.47,4624.27 6924.22,4624.68 5056.29,4626.32 5302.17,4629.47 3714.21,4635.42 1885.16,4637.02 6401.6,4638.88 6349.75,4641.72 1592.02,4650 1546.99,4651.5 1425.24,4654.17 6120.13,4659.52 6470.1,4660 1312.61,4665.26 5941.22,4668.67 5554.35,4677.02 1372.41,4683.04 4834.19,4688.22 4718.41,4691.06 5841.16,4690.3 6762.93,4691.96 5919.43,4693.09 4323.27,4698.35 4576.71,4698.57 1708.06,4699.68 6115.97,4712.52 3108.26,4719.92 4148.82,4719.46 1590.93,4722.2 1310.8,4726.08 1425.5,4727.89 4454.47,4728.92 3031.09,4731.14 3283.36,4734.99 5632.4,4753.74 5237.75,4756.4 4256,4759.66 5933.7,4759.87 3411.24,4763.59 6196.85,4763.77 6389.85,4763.11 2979.73,4764.79 6574.31,4765.54 1709.64,4768.04 3943.77,4767.69 5359.23,4770 6471.41,4769.28 898.45,4772.07 988.03,4772.4 5858.08,4773.02 5543.46,4778.98 4538.5,4781.06 6132.67,4781.04 1614.6,4781.69 3490.88,4794.05 3096.07,4796.99 6051.64,4798.87 1764.83,4804.23 3350.87,4817.6 5528.45,4819.82 1906.2,4823.66 6350.84,4824.36 1775.6,4834.61 2107.78,4834.19 2919.75,4835.87 4384.59,4843.87 6818.45,4844.86 4148.82,4845.25 4339,4852.52 4202.27,4854.73 4236.26,4854.43 4684.45,4855 3284.15,4855.32 4764.52,4858.25 6580.54,4860.78 1740.88,4865.26 1557,4868.07 5555.03,4868.44 6151.68,4868.13 1151.69,4870.95 1871.17,4870.45 1431.69,4879.74 1406.58,4880.88 4430.29,4883.24 4086.39,4884.67 6580.54,4886.44 4184.25,4888.87 1805.43,4889.16 4916.74,4889.77 5666.05,4892.02 1539.07,4896.87 6350.8,4897.69 5949.01,4904.45 3405.68,4908.94 5324.15,4909.02 5619.63,4908.23 4231.56,4913.18 1746.63,4915.16 2598.65,4915.69 1686.25,4927.76 6098.32,4929.6 1565.45,4930.73 6973.39,4932.68 1132.3,4947.61 5900.59,4953.83 5719.14,4955.39 6198.94,4955.6 6348.82,4955.41 3100.45,4956.16 2361.09,4957.23 2789.85,4959.01 5295.64,4968.66 3282.74,4971.51 1752.26,4977.93 5900.59,4978.2 5495.62,4983.57 5783.78,4985.44 6100.78,4985.44 5835.79,4986.5 1525.36,4987.25 2746.54,4998.9 1077.14,5000.26 3804.66,5005.3 4913.15,5006.16 6149.64,5007.37 2822.33,5012.82 6352.42,5019.55 6436.99,5019.57 3376.31,5021.69 5893.42,5023.23 1492.66,5028.98 4786.56,5028.58 3066.6,5029.74 6695.51,5031.46 2537.18,5034.97 1257.11,5036.98 1708,5041.49 1406.21,5042.1 790.3,5043.89 4617.79,5045.18 5638.09,5046.51 4684.31,5048.61 5472.1,5049.8 2716.71,5051.4 5925.32,5052.05 6111.47,5057.23 6389.02,5060.68 4887.92,5061.36 2237.26,5062.81 2456.86,5062.15 2674.51,5064.73 2152.57,5067.32 5754.04,5067.21 722.6,5068.47 4131.39,5069.99 880.06,5070.47 984.87,5073.98 6818.62,5077.72 6200.87,5091.55 4277.8,5092.65 1392.85,5094.23 1454.33,5099.26 5312.97,5102.63 2351.31,5105.83 6560.88,5107.26 7055.59,5107.8 1109.46,5114.42 5960.55,5115.92 5994.46,5117.31 5148.28,5121.46 5246.15,5129.82 907.51,5130.25 6491.92,5130.91 6064.28,5131.19 1604.18,5133.16 1415.64,5143.5 1259,5145.9 1535.1,5147.01 6583.15,5153.22 6923.67,5156.68 2833.48,5157.78 845.46,5160.74 5886.54,5160.28 6493.58,5173.22 5509.52,5174.88 767.23,5182.3 6981.03,5186.38 1051.53,5188.09 5354.14,5190.42 6290.77,5190.59 652.02,5191.13 3086.67,5192.15 3822.87,5192.38 2139.1,5196.89 2041.27,5198.38 5707.12,5198.17 913.06,5200.8 1791.06,5202.44 117.15,5211.28 1193.22,5213.52 3361.63,5214.63 5121.72,5215 1311.78,5217.72 4784.76,5218.35 6795.5,5220.99 253.76,5224.33 1542.15,5224.58 705.5,5226.79 5978.68,5232.35 6924.26,5232.68 5568.29,5233.97 5643.55,5234.7 582.21,5236.16 554.18,5237.2 763.12,5247.87 6400.03,5247.9 970.63,5248.22 6272.36,5248.15 2602.92,5256.03 5422.51,5258.01 4803.97,5261.5 326.96,5265.73 3861.8,5268.29 1123.58,5271.28 2833.48,5274.37 6203.39,5274.37 6274.43,5280.18 6558.43,5284.36 4704.68,5295.83 2455.55,5296.64 1693.79,5299.37 1464.75,5301 4865.88,5300.51 3899.82,5304.61 5333.8,5306.68 5143.88,5308.93 6610.48,5317.71 4022.8,5321.2 1913.98,5331.17 473.41,5332.94 2038.27,5332.16 1388.77,5333.74 6752.24,5336.07 2148.09,5353.13 2361.09,5354.14 214.88,5356.82 2901.99,5361.55 1289.91,5363.97 4322.7,5365.13 6936.86,5365.16 651.99,5371.82 2654.01,5373.93 2760.47,5374.99 4238.57,5375.46 6266.98,5379.36 6088.8,5387.44 2535.29,5389.04 1594.82,5390.62 5989.12,5392.31 1065.39,5411.7 1802.16,5421.52 2041.76,5426.01 6749.48,5427.24 6450.4,5434.42 2122.13,5445.48 1961.9,5447.47 6266.81,5448.11 1854.07,5449.47 5957.4,5450.22 6169.24,5451.95 2812.49,5462.01 6668.4,5462.95 6830.36,5462.45 90.85,5463.84 2354.58,5468.84 6351.07,5476.14 4242.35,5486.25 435.94,5488.85 2669.35,5489.01 5317.82,5490.72 5907.91,5491.62 2744.55,5492.48 7017.84,5496.29 6749.66,5499.61 4823.79,5503.51 4704.15,5504.59 6198.38,5512.05 3248.44,5520.79 2450.31,5522.61 314.91,5523.86 5647.41,5523.42 6393.2,5524.17 2870.44,5525.87 2919.66,5525.87 2968.87,5525.87 3126.65,5527.92 4288.92,5529.99 4338.13,5529.99 4387.35,5529.99 5861.53,5530.27 2314.99,5532.91 3030.49,5533.97 2203.16,5534.7 2232.6,5534.7 1456.91,5535.94 4226.67,5539.97 4449.05,5539.5 1257.8,5540.19 3936.7,5545.64 1775.7,5558.53 5643.3,5559.06 620.36,5567.93 2644.34,5568.32 2827.21,5570.53 5322.77,5573.78 5507.13,5576.07 5552.07,5579.24 3718.8,5586.06 3771.98,5586.06 3825.16,5586.06 6889.38,5585.72 6832.66,5587.2 1072.56,5592.67 5710.43,5594.32 4594.24,5600.79 4176.44,5601.55 2367.99,5602.64 3185.13,5608.43 6905.84,5612.84 3010.91,5613.13 3121.9,5613.95 3597.77,5614.38 6760.02,5615.12 4252.25,5616.44 5018.83,5619.11 1372.06,5620.19 2825,5620.68 4601.16,5625.53 4732.7,5626.42 191.88,5628.88 3434.35,5629.05 2641.63,5630.61 5509.05,5630.44 3875.45,5633.14 5767.09,5634.56 4439.9,5638.09 4889.89,5637.73 3718.8,5639.24 3771.98,5639.24 3825.16,5639.24 5571.19,5639.89 3191.92,5642.94 874.8,5646.92 3667.87,5647.39 2885.11,5650.08 4596.28,5649.94 3361.26,5652.47 5153.41,5656.22 2175.16,5664.86 5380.2,5664.43 1074.93,5668.11 3035.61,5668.49 5036.85,5675.5 3184.59,5679.34 6843.51,5680.91 759.01,5682.9 2540.96,5682.53 6881.49,5683.13 3058.63,5685.71 2279.14,5687.83 3121.8,5688.08 883.63,5688.34 2158.11,5689.27 3718.8,5692.42 3771.98,5692.42 3825.16,5692.42 5735.84,5693.84 5866.88,5697.2 2826.64,5698.57 1855.21,5700.36 1918.37,5702.24 540.96,5705.9 4464.96,5706.82 4650.35,5706.56 3210.4,5707.6 3322.16,5708.23 5439.9,5709.06 3276.69,5709.23 4215.53,5710.41 5127.06,5713.73 2982.44,5722.24 3045.54,5722.63 4545.17,5723.95 4688.44,5725.61 5322.77,5725.38 4294.39,5726.75 1029.11,5727.76 2802.3,5727.1 4374.23,5728.76 4136.65,5729.28 4616.12,5729.48 6984.53,5730.26 3244.75,5732.09 3619.19,5731.2 2890.41,5733.57 6761,5734.01 1260.45,5739.65 1389.37,5740.5 3651.17,5741.77 2155.23,5744.75 1791.2,5747.62 5580.47,5748.36 5498.51,5749.4 5645.84,5751.86 3279.68,5752.69 3213.12,5753.24 4756.77,5754.32 4982.09,5759.22 3327,5771.6 6664.85,5772.68 76.85,5774.92 5698.35,5777.48 1853.55,5778.95 3460.02,5780.3 4381.02,5783.05 4210.27,5783.35 4307.45,5784.26 2154.95,5787.88 390.93,5788.92 4470.03,5789.17 3659.83,5793.56 4129.56,5793.13 2974.54,5794.53 5806.4,5796.47 968.28,5798.07 6631.64,5799.95 1219.5,5802.41 4707.42,5808.04 6818.81,5809.48 2778.96,5817.08 2815.47,5817.01 2868.65,5816.13 2894.21,5817.01 2947.39,5816.13 3039.73,5816.99 3115.67,5817.08 2725.77,5817.96 3062.49,5817.96 5654.8,5817.12 2369.83,5819.01 3707.45,5820.08 3759.33,5820.95 678.97,5821.88 1908.1,5821.59 4197.43,5821.19 4233.94,5821.13 4458.2,5821.11 4480.96,5822.07 7041.71,5829.86 6924.28,5831.09 1301.18,5834.81 4802.49,5834.39 2179.63,5835.34 2312.57,5836.63 2725.09,5837.93 611.56,5839.55 3303.17,5842.36 2787.48,5844.04 4864.01,5843.33 5076.72,5843.33 2866.29,5844.38 4285.91,5850.08 5730.16,5853.82 3051.5,5856.44 2808.89,5858.72 4207.62,5858.3 4470.38,5858.19 4717.16,5860.8 3125.15,5867.38 3299.19,5870.88 4141.49,5872.32 6619.06,5876.04 2997.1,5877.51 4538.72,5877.57 4419.22,5880.78 4445.94,5880.78 1471.97,5882.85 1174.7,5883.48 2310.41,5884.19 4998.7,5884.34 5498.74,5884.66 4939.02,5886.67 5377.87,5887 3456.75,5887.14 921.88,5891.92 963.18,5892.02 5639.32,5891.67 5203.7,5892.89 1983.17,5894.52 6029.37,5894.93 6637.78,5895.14 471.72,5900.84 49.61,5903.9 304.82,5904.21 3052.55,5905.99 4469.17,5908.18 6785.24,5909.02 2039.99,5910.67 2404.44,5910.62 592.75,5917.96 3137.52,5918.74 695.36,5920.8 4740.04,5920.38 5696.39,5927.22 890.99,5931.31 956.33,5931.62 3190.84,5935.54 1414.1,5936.77 1540.61,5942.16 3090.79,5943.07 4508.02,5943.8 6994.1,5949.12 135.02,5952.31 3373.47,5956.24 1189.9,5958.9 5202.92,5958.27 2307.27,5960.88 5693.52,5962.09 926.52,5963.14 5321.43,5965.47 783.27,5966.78 1615.34,5967.78 5921.63,5972.79 5442.65,5977.16 2174.32,5978.12 2146.63,5979.48 6225.57,5981.69 1560.12,5993.74 4467.45,5994.17 2672.35,5995.85 4083.99,6008.6 6014.8,6012.7 3035.76,6021.51 2722.94,6022.79 2970.72,6023.53 6074.44,6023.57 1243.74,6025.42 2925.5,6025.62 4454.87,6025.28 4341.64,6027.63 5651.93,6028.17 4500.97,6033.55 2841.82,6036.66 4256.12,6036.72 4173.69,6042.86 4399.57,6044.42 2239.3,6046.13 490.14,6047.65 987.35,6047.65 1559.74,6047.15 1619.81,6048.93 302.91,6049.95 3428.62,6049.83 4794.84,6051.81 2171.25,6053.75 6392.9,6053.88 6453.43,6053.38 6511.69,6053.38 5558.36,6054.15 6334.89,6054.89 6571.12,6054.15 1957.94,6055.56 6216.11,6057.01 6267.88,6056.3 2508.54,6057.36 4117.76,6058.07 6762.25,6057.31 2089.85,6058.96 1468.93,6063.42 4347.87,6063.82 2928.8,6064.21 845.17,6066.89 7055.42,6069.27 4589.8,6071.85 3264.23,6072.47 3122.7,6075.02 4080.92,6074.13 5710.89,6074.75 4705.24,6075.77 4499.32,6080.81 3374.98,6091.1 696.15,6092.87 4104.34,6096.69 3963.09,6097.97 3922.27,6101.57 2171.01,6104.92 1565.93,6106.97 2678.65,6106.93 439.3,6126.91 1207.76,6126.31 587.16,6132.47 1019.82,6136.22 308.64,6138.96 2499.6,6139.19 1398.9,6152.23 6342.83,6153.48 6502.32,6155.05 898.16,6157.71 4215.53,6161.03 3027.62,6161.79 4503.17,6162.2 6167.18,6163.91 2900.51,6165.04 2767.64,6165.37 4348.65,6165.31 2528.28,6166.3 2659.38,6167.65 6611.25,6182.67 2640.98,6192.28 6754.39,6197.97 1247.53,6198.11 5832.75,6201.02 5863.74,6201.56 5802.02,6205.33 6087.05,6207.6 6119.15,6207.31 2202.84,6212.43 4338.92,6214.36 1818.2,6218.44 2273.16,6218.56 1508.44,6220.06 4724.73,6219.11 582.66,6221.76 1743.95,6221.14 4574.17,6222.54 1881.71,6224.53 1546.97,6228.47 1659.02,6228.2 1945.86,6228.54 2820.93,6228.91 797.08,6229.38 2026.62,6229.69 2076.26,6232.93 3186.1,6232.65 3003.84,6234.17 304.48,6235.27 3349.26,6240.9 4785.36,6242.07 4897.5,6241.48 5953.45,6250.76 6325.11,6250.95 6702.57,6250.57 6012.53,6252.02 6054.83,6252.88 5908.73,6254.52 6807.68,6254.86 7054.59,6256.52 6513.78,6258.25 2633.78,6259.21 5679.74,6259.36 5800.4,6260.32 3166.67,6263.06 6160.93,6262.94 5448.88,6263.83 5141.93,6264.81 2427.81,6265.44 2089.77,6266.91 4946.57,6266.85 2203.66,6267.34 1136.73,6269.62 1394.99,6269.62 1779.76,6269.78 4444.4,6269.63 2580.43,6271.26 897.52,6272.88 1551.85,6272.97 4229.94,6272.35 1657.94,6274.32 1900.61,6276.08 2497.48,6276.67 2007.14,6280.66 4642.61,6282.76
  other v2: 1680.11,440.59 1747.59,440.59 1715.26,454.69 1755.66,465.6 1674.4,466.89 1715.45,482.13 1717.87,632.29 1690.34,635.84 1743.35,635.17
GND_CHASE: C140.1 C166.1 CON3.15 CON3.16 R82.1 R115.1
  other v1: 35,3060.76 625.25,3063.35 197,3075.41 367.61,3076.27 509.78,3085.75 299.53,3129.7 424.48,3163.3 112.48,3224.34 336.59,3243.44 577.85,3246.88 200.44,3280.49 48.79,3289.97 517.54,3327.02 617.21,3337.37 112.48,3398.02 336.17,3399.69 478.96,3422.36 225.12,3462.02 52.24,3463.16 402.07,3468.34 611.54,3476.75 480.09,3542.48 89.13,3551.54 328.24,3557.21 617.21,3616.14 513.43,3643.77 174.13,3673.93 49.65,3682.89 352.72,3699.27 572.11,3717.25 95.93,3763.45 417.22,3828.79 576.87,3874.26 222.85,3889.24 355.44,3896.04 64.2,3901.7 506.9,3908.81 625.51,3952.5 140.13,3987.83 446.54,4001.9 284.05,4037.69 373.91,4105.22 162.15,4115.45 627.7,4221.21 81.91,4224.3 510.68,4235.41 264.36,4238.68 404.81,4247.76 580.19,4295.27 207.07,4312.04 482.28,4327.35 374.11,4342.23 78.44,4380.42 154.76,4423.44 633.53,4483.81 77.75,4491.44 157.54,4536.54 351.12,4574.79 628.67,4578.17 267.29,4582.91 533.66,4589.67 79.83,4602.45 437.66,4649.16 156.15,4650.33 278.11,4669.44 628.67,4703.07 77.75,4722.49 509.32,4731.52 231.78,4733.6 354.59,4737.07 149.21,4791.87 628.67,4802.98 433.44,4811.48 544.02,4868.84 75.66,4884.85 220.68,4889.71 350.12,4903.16 147.33,4960.76 314.58,4993.24 502.76,5014.43 70.85,5022.71 222.03,5022.93 383.67,5024.08 452.8,5099.67 309.05,5108.65 145.95,5110.03
GND_DC: CON1.2 FL2.2
"GPIO_A_0 / SDIO_B_RST": CON15.120 J51.1 SB3.2 SB4.1 | length 5039
  Top Layer w5: J51.1@820.44,5478.34 820.44,5571.36 ; CON15.120@3454.73,3666.88 3454.73,3724.75 3485.56,3755.58 3485.56,4540.89 v1(3632.7,4688.03)
  L6 w5: J51.1@831.5,5467.28 950.14,5348.63 1669.61,5348.63 2330.78,4687.46 3632.14,4687.46 v1(3632.7,4688.03) 3633.27,4687.46 4237.72,4687.46 v1(4323.6,4773.34)
"GPIO_B_4 / I2C_C_SCL / I2C_DISPLAY_CLK": CON15.117 J16.1 R513.1 | length 8005.6
  Top Layer w4: v1(4501.04,969.72) 4501.95,968.8 J16.1@4501.95,892.47 ; v1(5395.45,5277.03) 5415.84,5277.03 5577.95,5439.14 5652.09,5439.14 5692.91,5479.96 5692.91,5566.33 R513.1@5677.02,5582.21
  Top Layer w5: CON15.117@3435.04,3851.92 3435.04,3793.31 v1(3435.22,3793.14)
  L3 w4: v1(3590.79,5281.61) 3575.17,5281.61 3446.81,5153.25 3446.81,3804.73 v1(3435.22,3793.14) 3435.22,3760.18 3440.33,3755.07 3661.58,3533.81 3661.58,2555.63 3842.91,2374.3 3842.91,1838.19 4049.12,1631.98 4361.99,1631.98 4415.53,1685.52 4602.31,1685.52 v1(4617.09,1670.74)
  L6 w4: v1(3590.79,5281.61) 3590.79,5288.88 3652.67,5350.76 4211.29,5350.76 4287.81,5274.23 4378.51,5274.23 4455.04,5350.76 5321.72,5350.76 v1(5395.45,5277.03)
  Bottom Layer w4: v1(4501.04,969.72) 4532.37,1001.04 4651.87,1001.04 4682.79,1031.96 4682.79,1206.09 4646.03,1242.85 4646.03,1641.81 v1(4617.09,1670.74)
"GPIO_B_5 / I2C_C_SDA / I2C_DISPLAY_DAT": CON15.119 J16.3 R514.1 | length 7815.1
  Top Layer w4: J16.3@4601.95,892.47 4601.95,967.99 v1(4602.66,968.7) ; v1(5409.47,5293.64) 5563.99,5448.16 5645.55,5448.16 5677.02,5479.63 R514.1@5677.02,5494.63
  Top Layer w5: CON15.119@3454.73,3851.92 3454.73,3777.27 v1(3455.11,3776.88)
  L3 w4: v1(3573.51,5259.86) 3572.58,5260.79 3568.87,5260.79 3455.11,5147.03 v1(3455.11,3776.88) 3455.11,3755.07 3672.04,3538.15 3672.04,2559.96 3853.37,2378.63 3853.37,1842.52 4053.25,1642.64 4360.1,1642.64 4412.48,1695.01 4623.16,1695.01 v1(4630.57,1687.59)
  L6 w4: v1(3573.51,5259.86) 3573.51,5285.59 3647.88,5359.95 4214.85,5359.95 4291.56,5283.24 4372.79,5283.24 4449.5,5359.95 5343.16,5359.95 v1(5409.47,5293.64)
  Bottom Layer w4: v1(4602.66,968.7) 4624.05,990.09 4656.17,990.09 4691.95,1025.87 4691.95,1209.89 4656.79,1245.05 4656.79,1661.38 v1(4630.57,1687.59)
"GPIO_B_6 / LVDS_D_VDD_EN": CON13.28 CON16.74 J13.3 | length 6492
  Top Layer w4: v1(4575.46,3727.44) 4576.17,3726.73 CON16.74@4576.17,3668.45 ; J13.3@4687.06,522.73 4721.73,522.73 4752.06,553.06 4752.06,1002.68 v1(4735.52,1019.22) ; v1(4934.57,5292.43) 4929.55,5297.44 4929.55,5644.55 5128.32,5843.32 5128.32,6050.52 5143.98,6066.17 CON13.28@5143.98,6090.59
  L3 w4: v1(4575.46,3727.44) 4575.46,3750.03 4594.06,3768.63 4594.06,4210.63 4942.2,4558.78 4942.2,5284.79 v1(4934.57,5292.43)
  Bottom Layer w4: v1(4575.46,3727.44) 4586.36,3716.54 4586.36,3521.01 4630.09,3477.27 4744.43,3477.27 5204.46,3017.24 5204.46,1914.99 5240.98,1878.47 5240.98,1746.46 4720.03,1225.51 4720.03,1034.71 v1(4735.52,1019.22)
"GPIO_B_7 / LVDS_D_BL_EN": CON13.27 CON16.76 J13.2 | length 6858
  Top Layer w4: J13.2@4587.06,686.29 J13.2@4587.06,656.59 4587.06,572.47 4653.06,506.48 4653.06,464.9 4664.01,453.95 4719.12,453.95 4762.74,497.57 4762.74,1026.65 v1(4751.33,1038.06) v1@4751.2,1038.19 ; CON16.76@4596.56,3669.15 4596.56,3744.61 v1(4597.55,3745.6) ; v1(4950.08,5310.99) 4953.82,5314.74 4953.82,5647.87 5139.09,5833.14 5139.09,6040.12 5163.66,6064.7 CON13.27@5163.66,6090.59
  L3 w4: v1(4597.55,3745.6) 4605.63,3753.68 4605.63,4205.84 4954.42,4554.62 4954.42,5306.65 v1(4950.08,5310.99)
  Bottom Layer w4: v1(4597.55,3745.6) 4596.01,3744.05 4596.01,3524.65 4633.92,3486.74 4750.72,3486.74 5214.68,3022.78 5214.68,1921.37 5249.36,1886.69 5249.36,1737.91 4729.41,1217.96 4729.41,1059.97 v1(4751.33,1038.06)
GPIO_C_0/ETH_B_RST: CON15.11 J34.2 | length 2248.9
  Top Layer w5: v1@2391.73,3763.66 CON15.11@2391.73,3851.92
  Bottom Layer w5: J34.2@1337.86,5133.26 1384.16,5179.56 1595.64,5179.56 1937.11,4838.09 1937.11,4011.78 2205.73,3743.16 2371.42,3743.16 v1(2391.83,3763.57)
GPIO_C_1/ETH_B_INTR: CON15.7 J35.1 | length 2373.3
  Top Layer w5: v1@2352.36,3763.66 CON15.7@2352.36,3851.92
  Bottom Layer w5: J35.1@1178.25,5134.63 1239.97,5196.36 1433.81,5196.36 1602.85,5196.36 1953.91,4845.3 1953.91,4018.72 2218.27,3754.36 2343.26,3754.36 v1(2352.46,3763.57)
"GPIO_C_2 / RGB_VDD_EN / LVDS_E_VDD_EN": CON7.4 CON14.28 CON17.64 J20.3 | length 8576.5
  Top Layer w4: CON7.4@204.84,2845.17 821.76,2845.17 861.45,2805.49 987.99,2805.49 ; J20.3@987.99,3015.01 987.99,2805.49 ; CON17.64@2844.49,2750.44 v1(2844.49,2827.2) 2604.38,3067.31 2056.94,3067.31 1795.12,2805.49 987.99,2805.49 ; v1(6023.21,5988.78) 6041.5,6007.06 6129.34,6007.06 6157.39,6035.11 CON14.28@6157.39,6090.59
  Bottom Layer w4: v1(2844.49,2827.2) 2830.97,2840.72 2830.97,3065.4 2932.02,3166.45 3279.66,3166.45 3611.92,3498.71 3611.92,4021.58 3690.87,4100.53 3764.37,4100.53 3877.32,4213.47 4185.07,4213.47 5350.54,5378.93 5848.96,5378.93 5993.43,5523.4 5993.43,5974.35 6007.86,5988.78 v1(6023.21,5988.78)
"GPIO_C_3 / RGB_BL_EN / LVDS_E_BL_EN": CON7.5 CON17.66 J20.2 SB2.2 | length 8268.3
  Top Layer w4: CON7.5@204.84,2825.49 813.61,2825.49 857.47,2781.62 1795.12,2781.62 2068.56,3055.06 2604.03,3055.06 2821.32,2837.77 v1(2821.32,2818.66) 2824.81,2815.18 CON17.66@2824.81,2750.44 ; v1(1048.62,2863.65) 1070.49,2863.65 J20.2@1087.99,2881.15
  L3 w4: v1@1048.26,2781.62 v1(1048.62,2781.99) v1(1048.62,2863.65)
  Bottom Layer w4: v1(2821.32,2818.66) 2821.32,3072.53 2927.44,3178.64 3278.31,3178.64 3602.35,3502.68 3602.35,4025.55 3686.9,4110.1 3755.45,4110.1 3872.85,4227.5 4185.56,4227.5 5346.57,5388.51 5844.99,5388.51 5983.86,5527.37 5983.86,5961.48 5974.08,5971.26 v1(5948.67,5971.26)
"GPIO_C_4 / DSI_A_VDD_EN / LVDS_A_VDD_EN": CON6.28 CON18.80 J16.4 | length 3115.3
  Top Layer w5: v1(4222.78,1753.16) 4222.78,1691.06 4244.99,1668.84 4380.13,1668.84 4510.84,1538.13 4510.84,1204.96 4522.35,1193.45 4568.95,1193.45 4601.95,1160.45 J16.4@4601.95,1116.88 4601.95,1072.01 4573.02,1043.08 4514.37,1043.08 4427.62,956.33 4427.62,259.26 4435.44,251.43 CON6.28@4435.44,209.68
  Top Layer w6: CON18.80@4261.81,2750.44 v1@4261.81,2810.35
  L3 w5: v1(4222.78,1753.16) 4210.89,1765.06 4210.89,2180.63 4144.39,2247.12 4144.39,2571.66 4262,2689.26 v1(4262,2810.54)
